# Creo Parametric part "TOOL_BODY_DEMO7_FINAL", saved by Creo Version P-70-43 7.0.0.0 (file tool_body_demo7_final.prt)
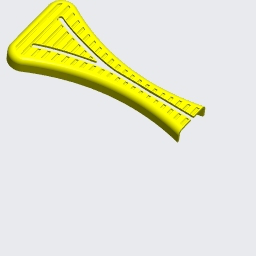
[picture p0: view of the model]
Units: millimeter Kilogram Sec (mmKs); MM, KILOGRAM, SECS
Materials in the file: NO_MATERIAL

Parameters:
  TITLE = "TITLE PARAMETER"
  DESCRIPTION = "DESCRIPTION PARAMETER"
  PART_NUMBER = "PARAMETER"
  DRAWN_BY = "PARAMETER"
  PROI_CREATED_BY = "nswadmin"
  PROI_CREATED_ON = "7/20/2004 11:43:31 AM"
  PROI_LOCATION = "Root Folder/Standards/Start Parts"
  AGILE_ITEM_NUMBER = "N/A"
  PTC_WM_ITERATION = "0"
  PTC_WM_VERSION = ".0"
  PTC_WM_CREATED_ON = "28-Aug-19 11:57:51 AM"
  PTC_WM_MODIFIED_ON = "28-Aug-19 11:57:51 AM"
  CATALOG_NUMBER = "XX####"

Created from: MARTIN.PRT

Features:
  1. datum plane "SIDE"
  2. datum plane "TOP"
  3. datum plane "FRONT"
  4. coordinate system
  5. protrusion
  6. round
  7. round "Round 3"
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
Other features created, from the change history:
  shell "Shell 1" (2 times)
  extruded cut "Extrude 3"
  extrusion "Extrude 4"
  chamfer "Chamfer 1"
  feature "Copy Geometry id 3942"
  extruded cut "Extrude 24"
  group "LOCAL_GROUP_20"
  feature "Body Subtract 1"
  feature "Extrude 32"

Other named items: CS0, BACK_ALL, BOTTOM_ALL, FRONT_ALL, LEFT_ALL, RIGHT_ALL, TOP_ALL, ANNOT_LAYER_STATE0001, ANNOT_LAYER_STATE0002, ANNOT_LAYER_STATE0003, ANNOT_LAYER_STATE0004, ANNOT_LAYER_STATE0005, ANNOT_LAYER_STATE0006

Layers: AXES, COPY_GEOMETRY, COSMETICS, DATUM_CSYS, DATUM_CURVES, DATUM_PLANES, DATUM_POINTS, SURFACES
